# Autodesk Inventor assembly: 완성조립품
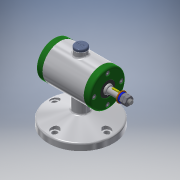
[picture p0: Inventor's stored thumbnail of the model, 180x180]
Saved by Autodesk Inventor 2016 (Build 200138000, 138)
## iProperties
Created: 2018-12
Part Number: 완성조립품
Material: 일반
Document SubType Name: Assembly
Designer: 605-17
Author: 605-17
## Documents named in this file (15)
- C:\Users\605-17\Desktop\481207V1029\완성조립품.iam
- C:\Users\605-17\Desktop\481207V1029\V벨트풀리.ipt
- C:\Users\605-17\Desktop\481207V1029\고무캡.ipt
- C:\Users\605-17\Desktop\481207V1029\너트 M8.ipt
- 너트 M8.ipt
- C:\Users\605-17\Desktop\481207V1029\뒤커버.ipt
- C:\Users\605-17\Desktop\481207V1029\베어링 15 x 32 x 9.ipt
- C:\Users\605-17\Desktop\481207V1029\본체.ipt
- C:\Users\605-17\Desktop\481207V1029\볼트 M4 x 12.ipt
- C:\Users\605-17\Desktop\481207V1029\스프링와셔 8.ipt
- C:\Users\605-17\Desktop\481207V1029\앞커버.ipt
- C:\Users\605-17\Desktop\481207V1029\오일 실 15 25 7.ipt
- C:\Users\605-17\Desktop\481207V1029\와셔 8x17.ipt
- C:\Users\605-17\Desktop\481207V1029\축.ipt
- C:\Users\605-17\Desktop\481207V1029\키 3 x 3 x 12.ipt
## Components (2 placed, 2 different names)
1. V벨트풀리:1
2. 고무캡:1 — 각도:3
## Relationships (1: Angle 1)
- 각도:3 [Angle]: 고무캡:1
